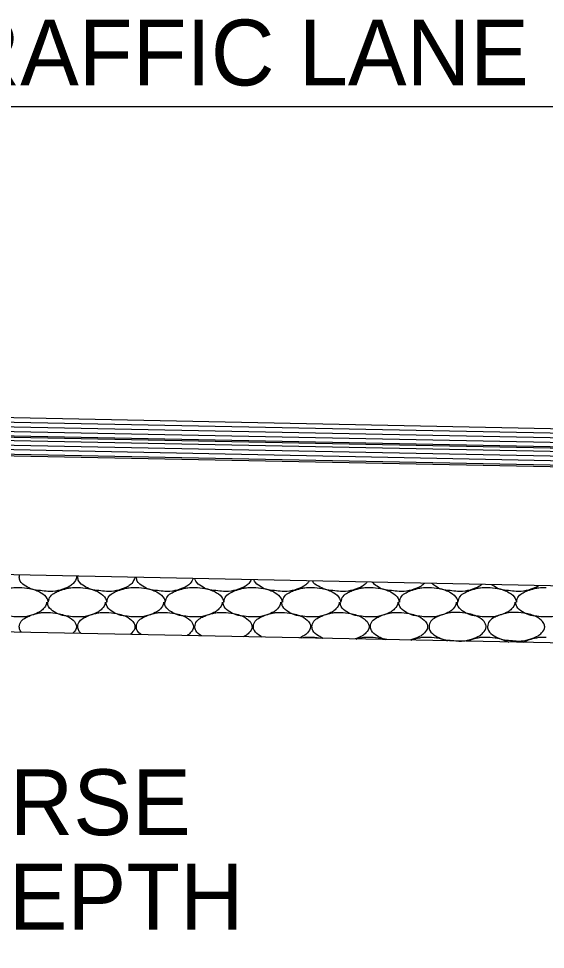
# Model space of a CAD drawing. Extents: x 1364961 to 1365294, y 367927 to 368034.
# Drawn here: x 1365210.07 to 1365214.68, y 367967.68 to 367975.83 of the extents above; entities that cross this region are included whole.
import ezdxf

# ---------------------------------------------------------------- set-up
doc = ezdxf.new("R2010")
doc.units = 0
doc.layers.add('Default', color=7, linetype='Continuous')

msp = doc.modelspace()

# ---------------------------------------------------------------- linework, layer by layer
at = {"layer": 'Default'}
for p, q in [((1365205.4981, 367975.0585), (1365217.487, 367975.0585)), ((1365229.476, 367971.9458), (1365193.4981, 367972.6644)), ((1365229.476, 367971.9058), (1365193.4991, 367972.6244)), ((1365229.476, 367971.8657), (1365193.4991, 367972.5844)), ((1365229.476, 367971.7758), (1365193.2513, 367972.4993)), ((1365229.476, 367971.8257), (1365193.5011, 367972.5444)), ((1365229.476, 367971.7857), (1365193.5011, 367972.5044)), ((1365229.476, 367971.7456), (1365193.5021, 367972.4644)), ((1365229.476, 367971.7056), (1365193.5031, 367972.4244)), ((1365229.476, 367971.6126), (1365193.4981, 367972.3314)), ((1365229.476, 367971.6656), (1365193.5031, 367972.3844)), ((1365229.476, 367971.6256), (1365193.5051, 367972.3444)), ((1365217.479, 367970.8114), (1365193.4921, 367971.2914)), ((1365210.0701, 367970.8514), (1365210.0761, 367970.8514)), ((1365210.5821, 367970.8514), (1365210.5881, 367970.8514)), ((1365211.0941, 367970.8514), (1365211.1001, 367970.8514)), ((1365211.6061, 367970.8514), (1365211.6121, 367970.8514)), ((1365212.1181, 367970.8514), (1365212.1241, 367970.8514)), ((1365212.6301, 367970.8514), (1365212.6361, 367970.8514)), ((1365213.1421, 367970.8514), (1365213.1481, 367970.8514)), ((1365213.6541, 367970.8514), (1365213.6601, 367970.8514)), ((1365214.1661, 367970.8514), (1365214.1721, 367970.8514)), ((1365214.6781, 367970.8514), (1365214.6841, 367970.8514)), ((1365217.479, 367970.3114), (1365193.4821, 367970.7914)), ((1365212.6301, 367970.4174), (1365212.6361, 367970.4174)), ((1365213.1421, 367970.4174), (1365213.1481, 367970.4174)), ((1365213.6541, 367970.4174), (1365213.6601, 367970.4174)), ((1365214.1661, 367970.4174), (1365214.1721, 367970.4174)), ((1365214.6781, 367970.4174), (1365214.6841, 367970.4174))]:
    msp.add_line(p, q, dxfattribs=at)
for points in [[(1365210.5761, 367970.9494), (1365210.5761, 367970.9414), (1365210.5481, 367970.8874), (1365210.5181, 367970.8634), (1365210.4561, 367970.8354), (1365210.3701, 367970.8174), (1365210.3261, 367970.8174), (1365210.2601, 367970.8234), (1365210.1881, 367970.8354), (1365210.1341, 367970.8614), (1365210.0841, 367970.9074), (1365210.0761, 367970.9414), (1365210.0781, 367970.9594)], [(1365211.0881, 367970.9394), (1365211.0601, 367970.8874), (1365211.0301, 367970.8634), (1365210.9681, 367970.8354), (1365210.8821, 367970.8174), (1365210.8381, 367970.8174), (1365210.7721, 367970.8234), (1365210.7001, 367970.8354), (1365210.6461, 367970.8614), (1365210.5961, 367970.9074), (1365210.5881, 367970.9414), (1365210.5891, 367970.9494)], [(1365211.5971, 367970.9294), (1365211.5721, 367970.8874), (1365211.5421, 367970.8634), (1365211.4801, 367970.8354), (1365211.3941, 367970.8174), (1365211.3501, 367970.8174), (1365211.2841, 367970.8234), (1365211.2121, 367970.8354), (1365211.1581, 367970.8614), (1365211.1081, 367970.9074), (1365211.1001, 367970.9394)], [(1365212.1051, 367970.9194), (1365212.0841, 367970.8874), (1365212.0541, 367970.8634), (1365211.9921, 367970.8354), (1365211.9061, 367970.8174), (1365211.8621, 367970.8174), (1365211.7961, 367970.8234), (1365211.7241, 367970.8354), (1365211.6701, 367970.8614), (1365211.6201, 367970.9074), (1365211.6121, 367970.9284)], [(1365209.8201, 367970.7234), (1365209.8201, 367970.7254), (1365209.8361, 367970.7734), (1365209.8761, 367970.8054), (1365209.9161, 367970.8234), (1365209.9761, 367970.8414), (1365210.0141, 367970.8494), (1365210.0701, 367970.8514)], [(1365210.0761, 367970.8514), (1365210.1641, 367970.8414), (1365210.2661, 367970.8054), (1365210.3181, 367970.7554), (1365210.3261, 367970.7254), (1365210.3261, 367970.7234)], [(1365210.3321, 367970.7234), (1365210.3321, 367970.7254), (1365210.3481, 367970.7734), (1365210.3881, 367970.8054), (1365210.4281, 367970.8234), (1365210.4881, 367970.8414), (1365210.5261, 367970.8494), (1365210.5821, 367970.8514)], [(1365210.5881, 367970.8514), (1365210.6761, 367970.8414), (1365210.7781, 367970.8054), (1365210.8301, 367970.7554), (1365210.8381, 367970.7254), (1365210.8381, 367970.7234)], [(1365210.8441, 367970.7234), (1365210.8441, 367970.7254), (1365210.8601, 367970.7734), (1365210.9001, 367970.8054), (1365210.9401, 367970.8234), (1365211.0001, 367970.8414), (1365211.0381, 367970.8494), (1365211.0941, 367970.8514)], [(1365211.1001, 367970.8514), (1365211.1881, 367970.8414), (1365211.2901, 367970.8054), (1365211.3421, 367970.7554), (1365211.3501, 367970.7254), (1365211.3501, 367970.7234)], [(1365211.3561, 367970.7234), (1365211.3561, 367970.7254), (1365211.3721, 367970.7734), (1365211.4121, 367970.8054), (1365211.4521, 367970.8234), (1365211.5121, 367970.8414), (1365211.5501, 367970.8494), (1365211.6061, 367970.8514)], [(1365211.6121, 367970.8514), (1365211.7001, 367970.8414), (1365211.8021, 367970.8054), (1365211.8541, 367970.7554), (1365211.8621, 367970.7254), (1365211.8621, 367970.7234)], [(1365211.8681, 367970.7234), (1365211.8681, 367970.7254), (1365211.8841, 367970.7734), (1365211.9241, 367970.8054), (1365211.9641, 367970.8234), (1365212.0241, 367970.8414), (1365212.0621, 367970.8494), (1365212.1181, 367970.8514)], [(1365212.1241, 367970.8514), (1365212.2121, 367970.8414), (1365212.3141, 367970.8054), (1365212.3661, 367970.7554), (1365212.3741, 367970.7254), (1365212.3741, 367970.7234)], [(1365212.6121, 367970.9084), (1365212.5961, 367970.8874), (1365212.5661, 367970.8634), (1365212.5041, 367970.8354), (1365212.4181, 367970.8174), (1365212.3741, 367970.8174), (1365212.3081, 367970.8234), (1365212.2361, 367970.8354), (1365212.1821, 367970.8614), (1365212.1321, 367970.9074), (1365212.1271, 367970.9184)], [(1365212.3801, 367970.7234), (1365212.3801, 367970.7254), (1365212.3961, 367970.7734), (1365212.4361, 367970.8054), (1365212.4761, 367970.8234), (1365212.5361, 367970.8414), (1365212.5741, 367970.8494), (1365212.6301, 367970.8514)], [(1365212.6361, 367970.8514), (1365212.7241, 367970.8414), (1365212.8261, 367970.8054), (1365212.8781, 367970.7554), (1365212.8861, 367970.7254), (1365212.8861, 367970.7234)], [(1365213.1171, 367970.8984), (1365213.1081, 367970.8874), (1365213.0781, 367970.8634), (1365213.0161, 367970.8354), (1365212.9301, 367970.8174), (1365212.8861, 367970.8174), (1365212.8201, 367970.8234), (1365212.7481, 367970.8354), (1365212.6941, 367970.8614), (1365212.6441, 367970.9074), (1365212.6441, 367970.9084)], [(1365212.8921, 367970.7234), (1365212.8921, 367970.7254), (1365212.9081, 367970.7734), (1365212.9481, 367970.8054), (1365212.9881, 367970.8234), (1365213.0481, 367970.8414), (1365213.0861, 367970.8494), (1365213.1421, 367970.8514)], [(1365213.1481, 367970.8514), (1365213.2361, 367970.8414), (1365213.3381, 367970.8054), (1365213.3901, 367970.7554), (1365213.3981, 367970.7254), (1365213.3981, 367970.7234)], [(1365213.6211, 367970.8884), (1365213.6201, 367970.8874), (1365213.5901, 367970.8634), (1365213.5281, 367970.8354), (1365213.4421, 367970.8174), (1365213.3981, 367970.8174), (1365213.3321, 367970.8234), (1365213.2601, 367970.8354), (1365213.2061, 367970.8614), (1365213.1631, 367970.8974)], [(1365213.4041, 367970.7234), (1365213.4041, 367970.7254), (1365213.4201, 367970.7734), (1365213.4601, 367970.8054), (1365213.5001, 367970.8234), (1365213.5601, 367970.8414), (1365213.5981, 367970.8494), (1365213.6541, 367970.8514)], [(1365213.6601, 367970.8514), (1365213.7481, 367970.8414), (1365213.8501, 367970.8054), (1365213.9021, 367970.7554), (1365213.9101, 367970.7254), (1365213.9101, 367970.7234)], [(1365214.1231, 367970.8784), (1365214.1021, 367970.8634), (1365214.0401, 367970.8354), (1365213.9541, 367970.8174), (1365213.9101, 367970.8174), (1365213.8441, 367970.8234), (1365213.7721, 367970.8354), (1365213.7181, 367970.8614), (1365213.6841, 367970.8874)], [(1365213.9161, 367970.7234), (1365213.9161, 367970.7254), (1365213.9321, 367970.7734), (1365213.9721, 367970.8054), (1365214.0121, 367970.8234), (1365214.0721, 367970.8414), (1365214.1101, 367970.8494), (1365214.1661, 367970.8514)], [(1365214.1721, 367970.8514), (1365214.2601, 367970.8414), (1365214.3621, 367970.8054), (1365214.4141, 367970.7554), (1365214.4221, 367970.7254), (1365214.4221, 367970.7234)], [(1365214.6221, 367970.8684), (1365214.6141, 367970.8634), (1365214.5521, 367970.8354), (1365214.4661, 367970.8174), (1365214.4221, 367970.8174), (1365214.3561, 367970.8234), (1365214.2841, 367970.8354), (1365214.2301, 367970.8614), (1365214.2081, 367970.8764)], [(1365214.4281, 367970.7234), (1365214.4281, 367970.7254), (1365214.4441, 367970.7734), (1365214.4841, 367970.8054), (1365214.5241, 367970.8234), (1365214.5841, 367970.8414), (1365214.6221, 367970.8494), (1365214.6781, 367970.8514)], [(1365210.0701, 367970.5934), (1365210.0621, 367970.5934), (1365209.9961, 367970.5994), (1365209.9241, 367970.6114), (1365209.8701, 367970.6374), (1365209.8201, 367970.6834), (1365209.8121, 367970.7174), (1365209.8121, 367970.7234)], [(1365210.3141, 367970.7234), (1365210.3141, 367970.7174), (1365210.2861, 367970.6634), (1365210.2561, 367970.6394), (1365210.1941, 367970.6114), (1365210.1081, 367970.5934), (1365210.0701, 367970.5934)], [(1365210.5821, 367970.5934), (1365210.5741, 367970.5934), (1365210.5081, 367970.5994), (1365210.4361, 367970.6114), (1365210.3821, 367970.6374), (1365210.3321, 367970.6834), (1365210.3241, 367970.7174), (1365210.3241, 367970.7234)], [(1365210.8261, 367970.7234), (1365210.8261, 367970.7174), (1365210.7981, 367970.6634), (1365210.7681, 367970.6394), (1365210.7061, 367970.6114), (1365210.6201, 367970.5934), (1365210.5821, 367970.5934)], [(1365211.0941, 367970.5934), (1365211.0861, 367970.5934), (1365211.0201, 367970.5994), (1365210.9481, 367970.6114), (1365210.8941, 367970.6374), (1365210.8441, 367970.6834), (1365210.8361, 367970.7174), (1365210.8361, 367970.7234)], [(1365211.3381, 367970.7234), (1365211.3381, 367970.7174), (1365211.3101, 367970.6634), (1365211.2801, 367970.6394), (1365211.2181, 367970.6114), (1365211.1321, 367970.5934), (1365211.0941, 367970.5934)], [(1365211.6061, 367970.5934), (1365211.5981, 367970.5934), (1365211.5321, 367970.5994), (1365211.4601, 367970.6114), (1365211.4061, 367970.6374), (1365211.3561, 367970.6834), (1365211.3481, 367970.7174), (1365211.3481, 367970.7234)], [(1365211.8501, 367970.7234), (1365211.8501, 367970.7174), (1365211.8221, 367970.6634), (1365211.7921, 367970.6394), (1365211.7301, 367970.6114), (1365211.6441, 367970.5934), (1365211.6061, 367970.5934)], [(1365212.1181, 367970.5934), (1365212.1101, 367970.5934), (1365212.0441, 367970.5994), (1365211.9721, 367970.6114), (1365211.9181, 367970.6374), (1365211.8681, 367970.6834), (1365211.8601, 367970.7174), (1365211.8601, 367970.7234)], [(1365212.3621, 367970.7234), (1365212.3621, 367970.7174), (1365212.3341, 367970.6634), (1365212.3041, 367970.6394), (1365212.2421, 367970.6114), (1365212.1561, 367970.5934), (1365212.1181, 367970.5934)], [(1365212.6301, 367970.5934), (1365212.6221, 367970.5934), (1365212.5561, 367970.5994), (1365212.4841, 367970.6114), (1365212.4301, 367970.6374), (1365212.3801, 367970.6834), (1365212.3721, 367970.7174), (1365212.3721, 367970.7234)], [(1365212.8741, 367970.7234), (1365212.8741, 367970.7174), (1365212.8461, 367970.6634), (1365212.8161, 367970.6394), (1365212.7541, 367970.6114), (1365212.6681, 367970.5934), (1365212.6301, 367970.5934)], [(1365213.1421, 367970.5934), (1365213.1341, 367970.5934), (1365213.0681, 367970.5994), (1365212.9961, 367970.6114), (1365212.9421, 367970.6374), (1365212.8921, 367970.6834), (1365212.8841, 367970.7174), (1365212.8841, 367970.7234)], [(1365213.3861, 367970.7234), (1365213.3861, 367970.7174), (1365213.3581, 367970.6634), (1365213.3281, 367970.6394), (1365213.2661, 367970.6114), (1365213.1801, 367970.5934), (1365213.1421, 367970.5934)], [(1365213.6541, 367970.5934), (1365213.6461, 367970.5934), (1365213.5801, 367970.5994), (1365213.5081, 367970.6114), (1365213.4541, 367970.6374), (1365213.4041, 367970.6834), (1365213.3961, 367970.7174), (1365213.3961, 367970.7234)], [(1365213.8981, 367970.7234), (1365213.8981, 367970.7174), (1365213.8701, 367970.6634), (1365213.8401, 367970.6394), (1365213.7781, 367970.6114), (1365213.6921, 367970.5934), (1365213.6541, 367970.5934)], [(1365214.1661, 367970.5934), (1365214.1581, 367970.5934), (1365214.0921, 367970.5994), (1365214.0201, 367970.6114), (1365213.9661, 367970.6374), (1365213.9161, 367970.6834), (1365213.9081, 367970.7174), (1365213.9081, 367970.7234)], [(1365214.4101, 367970.7234), (1365214.4101, 367970.7174), (1365214.3821, 367970.6634), (1365214.3521, 367970.6394), (1365214.2901, 367970.6114), (1365214.2041, 367970.5934), (1365214.1661, 367970.5934)], [(1365214.6781, 367970.5934), (1365214.6701, 367970.5934), (1365214.6041, 367970.5994), (1365214.5321, 367970.6114), (1365214.4781, 367970.6374), (1365214.4281, 367970.6834), (1365214.4201, 367970.7174), (1365214.4201, 367970.7234)], [(1365214.9221, 367970.7234), (1365214.9221, 367970.7174), (1365214.8941, 367970.6634), (1365214.8641, 367970.6394), (1365214.8021, 367970.6114), (1365214.7161, 367970.5934), (1365214.6781, 367970.5934)], [(1365210.0951, 367970.4594), (1365210.0841, 367970.4734), (1365210.0761, 367970.5074), (1365210.0921, 367970.5554), (1365210.1321, 367970.5874), (1365210.1721, 367970.6054), (1365210.2321, 367970.6234), (1365210.2701, 367970.6314), (1365210.3261, 367970.6334)], [(1365210.3261, 367970.6334), (1365210.4141, 367970.6234), (1365210.5161, 367970.5874), (1365210.5681, 367970.5374), (1365210.5761, 367970.5074), (1365210.5481, 367970.4534), (1365210.5451, 367970.4504)], [(1365210.6171, 367970.4484), (1365210.5961, 367970.4734), (1365210.5881, 367970.5074), (1365210.6041, 367970.5554), (1365210.6441, 367970.5874), (1365210.6841, 367970.6054), (1365210.7441, 367970.6234), (1365210.7821, 367970.6314), (1365210.8381, 367970.6334)], [(1365210.8381, 367970.6334), (1365210.9261, 367970.6234), (1365211.0281, 367970.5874), (1365211.0801, 367970.5374), (1365211.0881, 367970.5074), (1365211.0601, 367970.4534), (1365211.0461, 367970.4404)], [(1365211.1421, 367970.4384), (1365211.1081, 367970.4734), (1365211.1001, 367970.5074), (1365211.1161, 367970.5554), (1365211.1561, 367970.5874), (1365211.1961, 367970.6054), (1365211.2561, 367970.6234), (1365211.2941, 367970.6314), (1365211.3501, 367970.6334)], [(1365211.3501, 367970.6334), (1365211.4381, 367970.6234), (1365211.5401, 367970.5874), (1365211.5921, 367970.5374), (1365211.6001, 367970.5074), (1365211.5721, 367970.4534), (1365211.5431, 367970.4304)], [(1365211.6701, 367970.4274), (1365211.6201, 367970.4734), (1365211.6121, 367970.5074), (1365211.6281, 367970.5554), (1365211.6681, 367970.5874), (1365211.7081, 367970.6054), (1365211.7681, 367970.6234), (1365211.8061, 367970.6314), (1365211.8621, 367970.6334)], [(1365211.8621, 367970.6334), (1365211.9501, 367970.6234), (1365212.0521, 367970.5874), (1365212.1041, 367970.5374), (1365212.1121, 367970.5074), (1365212.0841, 367970.4534), (1365212.0541, 367970.4294), (1365212.0371, 367970.4204)], [(1365212.1991, 367970.4174), (1365212.1821, 367970.4274), (1365212.1321, 367970.4734), (1365212.1241, 367970.5074), (1365212.1401, 367970.5554), (1365212.1801, 367970.5874), (1365212.2201, 367970.6054), (1365212.2801, 367970.6234), (1365212.3181, 367970.6314), (1365212.3741, 367970.6334)], [(1365212.3741, 367970.6334), (1365212.4621, 367970.6234), (1365212.5641, 367970.5874), (1365212.6161, 367970.5374), (1365212.6241, 367970.5074), (1365212.5961, 367970.4534), (1365212.5661, 367970.4294), (1365212.5281, 367970.4104)], [(1365212.7321, 367970.4064), (1365212.6941, 367970.4274), (1365212.6441, 367970.4734), (1365212.6361, 367970.5074), (1365212.6521, 367970.5554), (1365212.6921, 367970.5874), (1365212.7321, 367970.6054), (1365212.7921, 367970.6234), (1365212.8301, 367970.6314), (1365212.8861, 367970.6334)], [(1365212.8861, 367970.6334), (1365212.9741, 367970.6234), (1365213.0761, 367970.5874), (1365213.1281, 367970.5374), (1365213.1361, 367970.5074), (1365213.1081, 367970.4534), (1365213.0781, 367970.4294), (1365213.0161, 367970.4014), (1365213.0141, 367970.4004)], [(1365213.2911, 367970.3954), (1365213.2601, 367970.4014), (1365213.2061, 367970.4274), (1365213.1561, 367970.4734), (1365213.1481, 367970.5074), (1365213.1641, 367970.5554), (1365213.2041, 367970.5874), (1365213.2441, 367970.6054), (1365213.3041, 367970.6234), (1365213.3421, 367970.6314), (1365213.3981, 367970.6334)], [(1365213.3981, 367970.6334), (1365213.4861, 367970.6234), (1365213.5881, 367970.5874), (1365213.6401, 367970.5374), (1365213.6481, 367970.5074), (1365213.6201, 367970.4534), (1365213.5901, 367970.4294), (1365213.5281, 367970.4014), (1365213.4921, 367970.3914)], [(1365213.9101, 367970.6334), (1365213.9981, 367970.6234), (1365214.1001, 367970.5874), (1365214.1521, 367970.5374), (1365214.1601, 367970.5074), (1365214.1321, 367970.4534), (1365214.1021, 367970.4294), (1365214.0401, 367970.4014), (1365213.9541, 367970.3834), (1365213.9101, 367970.3834), (1365213.8441, 367970.3894), (1365213.7721, 367970.4014), (1365213.7181, 367970.4274), (1365213.6681, 367970.4734), (1365213.6601, 367970.5074), (1365213.6761, 367970.5554), (1365213.7161, 367970.5874), (1365213.7561, 367970.6054), (1365213.8161, 367970.6234), (1365213.8541, 367970.6314), (1365213.9101, 367970.6334)], [(1365214.4221, 367970.6334), (1365214.5101, 367970.6234), (1365214.6121, 367970.5874), (1365214.6641, 367970.5374), (1365214.6721, 367970.5074), (1365214.6441, 367970.4534), (1365214.6141, 367970.4294), (1365214.5521, 367970.4014), (1365214.4661, 367970.3834), (1365214.4221, 367970.3834), (1365214.3561, 367970.3894), (1365214.2841, 367970.4014), (1365214.2301, 367970.4274), (1365214.1801, 367970.4734), (1365214.1721, 367970.5074), (1365214.1881, 367970.5554), (1365214.2281, 367970.5874), (1365214.2681, 367970.6054), (1365214.3281, 367970.6234), (1365214.3661, 367970.6314), (1365214.4221, 367970.6334)], [(1365212.5471, 367970.4104), (1365212.5741, 367970.4154), (1365212.6301, 367970.4174)], [(1365212.6361, 367970.4174), (1365212.7241, 367970.4074), (1365212.7291, 367970.4064)], [(1365213.0231, 367970.4004), (1365213.0481, 367970.4074), (1365213.0861, 367970.4154), (1365213.1421, 367970.4174)], [(1365213.1481, 367970.4174), (1365213.2361, 367970.4074), (1365213.2821, 367970.3954)], [(1365213.5041, 367970.3914), (1365213.5601, 367970.4074), (1365213.5981, 367970.4154), (1365213.6541, 367970.4174)], [(1365213.6601, 367970.4174), (1365213.7481, 367970.4074), (1365213.8231, 367970.3844)], [(1365213.9921, 367970.3814), (1365214.0121, 367970.3894), (1365214.0721, 367970.4074), (1365214.1101, 367970.4154), (1365214.1661, 367970.4174)], [(1365214.1721, 367970.4174), (1365214.2601, 367970.4074), (1365214.3571, 367970.3734)], [(1365214.4841, 367970.3714), (1365214.5241, 367970.3894), (1365214.5841, 367970.4074), (1365214.6221, 367970.4154), (1365214.6781, 367970.4174)]]:
    msp.add_spline(points, degree=3, dxfattribs=at)

# ---------------------------------------------------------------- texts
for s, p in [('12\'-0" TRAFFIC LANE', (1365206.8802, 367975.2435)), ('AGGREGATE BASE COURSE', (1365200.9181, 367968.6842)), ('(CLASS 7)- 6" COMP\'D. DEPTH', (1365200.9181, 367967.8582))]:
    msp.add_text(s, height=0.576, dxfattribs=at).set_placement(p)

doc.saveas('drawing.dxf')
